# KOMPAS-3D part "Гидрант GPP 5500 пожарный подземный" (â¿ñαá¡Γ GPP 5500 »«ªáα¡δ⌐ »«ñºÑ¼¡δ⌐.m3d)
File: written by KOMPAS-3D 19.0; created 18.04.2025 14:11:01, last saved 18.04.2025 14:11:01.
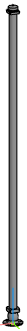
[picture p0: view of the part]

Document properties: Полное имя файла: E:\Dendor Работа Сачек\3D для проекитирвщиков\11.1 Тип GPP. Гидрант пожарный подземный\stp_Тип GPP. 750-6000 Гидрант пожарный подземный\Гидрант GPP 5500 пожарный подземный.m3d

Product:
- Part/product: Гидрант GPP 5500 пожарный подземный

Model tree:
1. Операция без истории:1  (labels: Гидрант GPP 5500 пожарный подземный)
